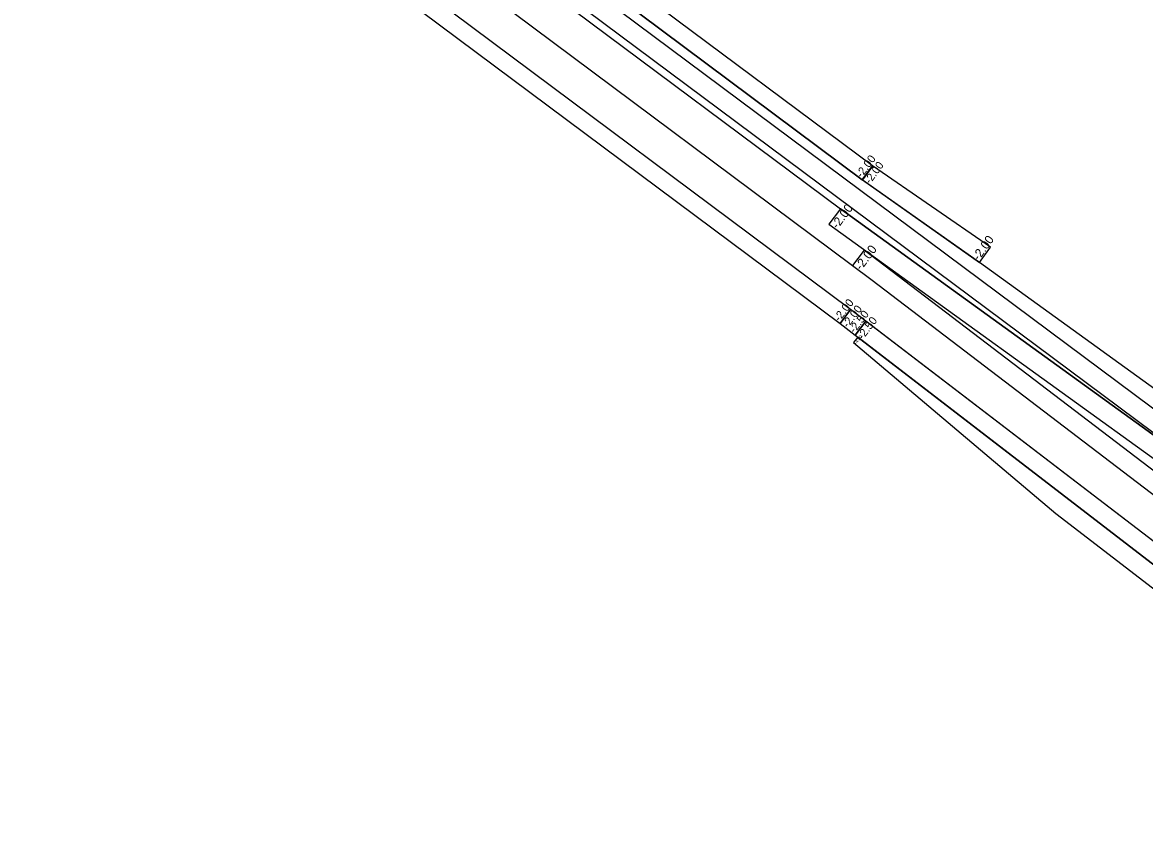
# Model space of a CAD drawing. Extents: x 2342222 to 2351711, y 366548 to 372860.
# Drawn here: x 2342929 to 2343637, y 371541 to 372059 of the extents above; entities that cross this region are included whole.
import ezdxf

# ---------------------------------------------------------------- set-up
doc = ezdxf.new("R2010")
doc.units = 0
for name, color, linetype in [('RD_PD_PaveShd', 7, 'Continuous'), ('RD_PD_SuperShp_BL_EB_526', 7, 'Continuous'), ('RD_PD_SuperShp_BL_WB_526', 7, 'Continuous'), ('RD_PD_SuperShp_WB_526', 7, 'Continuous')]:
    doc.layers.add(name, color=color, linetype=linetype)

msp = doc.modelspace()

# ---------------------------------------------------------------- linework, layer by layer
at = {"layer": 'RD_PD_PaveShd'}
for p, q in [((2343444.88, 371941.48), (2343437.71, 371931.86)), ((2343437.71, 371931.86), (2344136.54, 371426.71))]:
    msp.add_line(p, q, dxfattribs=at)
at = {"layer": 'RD_PD_SuperShp_BL_EB_526'}
for p, q in [((2342242.24, 372809.14), (2343465.01, 371896.51)), ((2343451.25, 371878.08), (2342228.48, 372790.71)), ((2343451.25, 371878.08), (2342228.48, 372790.71)), ((2342221.9, 372781.89), (2343444.67, 371869.26)), ((2343459.82, 371915.57), (2343452.54, 371905.82)), ((2344440.98, 371166.63), (2343459.82, 371915.57)), ((2343452.54, 371905.82), (2343465.01, 371896.51)), ((2343465.01, 371896.51), (2343853.9, 371599.66)), ((2343465.01, 371896.51), (2344433.75, 371157.05)), ((2343444.67, 371869.26), (2343451.35, 371878)), ((2343451.35, 371878), (2343444.67, 371869.26)), ((2343839.34, 371580.58), (2343451.25, 371878.08)), ((2343451.35, 371878), (2343451.25, 371878.08)), ((2343460.87, 371870.7), (2343451.35, 371878)), ((2343444.67, 371869.26), (2343454.18, 371861.94)), ((2343454.18, 371861.94), (2343460.87, 371870.7)), ((2343460.87, 371870.7), (2343454.18, 371861.94)), ((2343839.34, 371580.58), (2343460.87, 371870.7)), ((2343455.81, 371860.69), (2343453.2, 371857.27)), ((2343453.2, 371857.27), (2343580.73, 371749.38)), ((2343454.18, 371861.94), (2343832.06, 371571.04)), ((2343832.06, 371571.04), (2343455.81, 371860.69)), ((2343580.73, 371749.38), (2343824.76, 371561.52))]:
    msp.add_line(p, q, dxfattribs=at)
at = {"layer": 'RD_PD_SuperShp_BL_WB_526'}
for p, q in [((2343465.22, 371968.72), (2342276.93, 372855.62)), ((2343458.64, 371959.91), (2342270.35, 372846.81)), ((2342270.35, 372846.81), (2343458.64, 371959.91)), ((2342256.59, 372828.37), (2343444.88, 371941.48)), ((2343458.64, 371959.91), (2343465.22, 371968.72)), ((2343458.64, 371959.91), (2343465.22, 371968.72)), ((2343465.07, 371968.52), (2343458.78, 371959.81)), ((2343465.22, 371968.72), (2343465.07, 371968.52)), ((2343539.62, 371917.41), (2343465.22, 371968.72)), ((2343444.88, 371941.48), (2343437.71, 371931.86)), ((2343444.88, 371941.48), (2344143.65, 371436.38)), ((2344143.65, 371436.38), (2343444.88, 371941.48)), ((2343437.71, 371931.86), (2344136.54, 371426.71)), ((2343532.59, 371907.69), (2343539.62, 371917.41))]:
    msp.add_line(p, q, dxfattribs=at)
for points in [[(2344157.85, 371455.72), (2343532.6, 371907.69), (2343458.64, 371959.91)], [(2343458.78, 371959.81), (2343532.59, 371907.69)]]:
    msp.add_lwpolyline(points, dxfattribs=at)
at = {"layer": 'RD_PD_SuperShp_WB_526'}
for p, q in [((2345214.29, 370642.07), (2342246.73, 372856.95)), ((2342239.55, 372847.33), (2345207.11, 370632.45))]:
    msp.add_line(p, q, dxfattribs=at)

# ---------------------------------------------------------------- texts
at = {"layer": 'RD_PD_SuperShp_BL_EB_526'}
for s, height, rotation, p in [('-2.00', 5.598, 53.26372, (2343458, 371902.35)), ('-2.00', 5.06, 52.64469, (2343444.31, 371870.05)), ('-2.00', 5.06, 52.63457, (2343449.57, 371866.06)), ('-2.50', 5.071, 52.64469, (2343453.85, 371862.77)), ('-2.50', 5.071, 52.64469, (2343459.09, 371858.73)), ('-4.00', 1.977, 52.64991, (2343455.07, 371855.98))]:
    msp.add_text(s, height=height, rotation=rotation, dxfattribs=at).set_placement(p)
at = {"layer": 'RD_PD_SuperShp_BL_WB_526'}
for height, rotation, p in [(5.06, 53.26372, (2343458.29, 371960.72)), (4.941, 54.13871, (2343463.66, 371956.86)), (5.521, 53.26372, (2343443.12, 371928.48)), (5.52, 54.12399, (2343532.17, 371908.54))]:
    msp.add_text('-2.00', height=height, rotation=rotation, dxfattribs=at).set_placement(p)

doc.saveas('drawing.dxf')
